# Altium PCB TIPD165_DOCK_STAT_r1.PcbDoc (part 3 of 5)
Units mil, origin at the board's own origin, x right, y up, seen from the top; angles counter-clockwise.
Board outline 6950 x 2800 mil, 2 copper layers (Primary Side, Secondary Side), stack 12.7 mil thick; 32 components, 163 nets, 1211 pads, 80 vias.
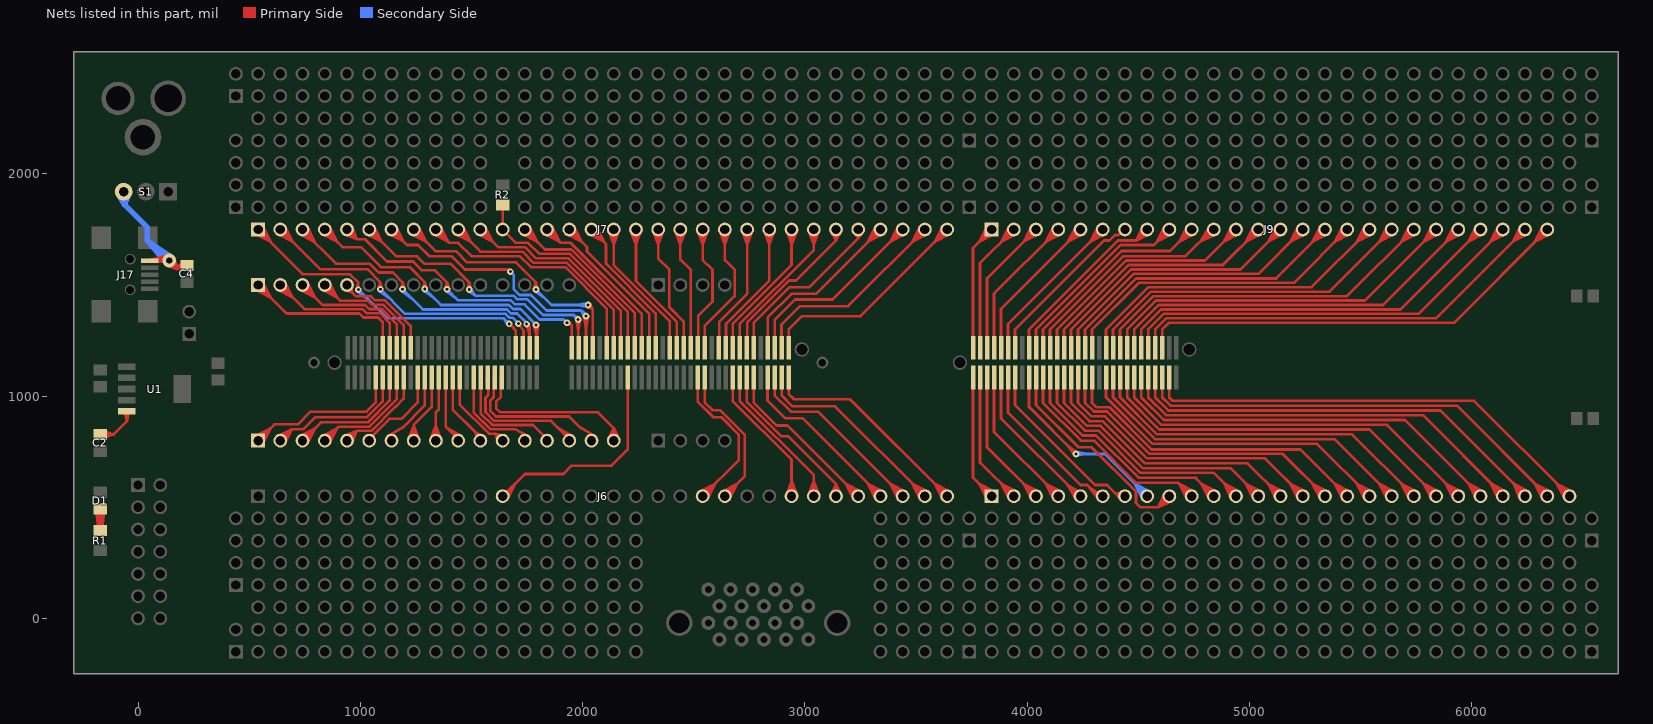
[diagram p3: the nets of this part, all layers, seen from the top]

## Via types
v1: diameter 30/30 (per signal layer), hole 13, Primary Side to Secondary Side, 70 vias
v2: diameter 62/62 (per signal layer), hole 28, Primary Side to Secondary Side, 9 vias
v3: diameter 30, hole 13, Primary Side to Secondary Side, 1 vias

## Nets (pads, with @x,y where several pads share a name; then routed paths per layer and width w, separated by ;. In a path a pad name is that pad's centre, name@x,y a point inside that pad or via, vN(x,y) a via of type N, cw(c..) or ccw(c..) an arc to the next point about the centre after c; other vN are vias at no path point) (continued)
$$$5944: J6.25 pad.103@2675.28,1084 | length 911.6
  Primary Side w12: pad.103@2675.28,1084 2675.28,978.72 2940,714 J6.25@2940,550 ; J6.25@2915.44,554.66 2940,617 ; J6.25@2927.06,551.26 2940,617 ; J6.25@2952.94,551.26 2940,617 ; J6.25@2964.56,554.66 2940,617
$$$5949: J6.26 pad.105@2706.78,1084 | length 940
  Primary Side w12: pad.105@2706.78,1084 2706.78,978.72 3040,645.5 J6.26@3040,550 ; J6.26@3015.44,554.66 3040,617 ; J6.26@3027.06,551.26 3040,617 ; J6.26@3052.94,551.26 3040,617 ; J6.26@3064.56,554.66 3040,617
$$$5959: J6.27 pad.107@2738.28,1084 | length 938.8
  Primary Side w12: pad.107@2738.28,1084 2738.28,975.26 2893.53,820 2925,820 3140,605 ; J6.27@3115.65,555.68 3140,605 ; J6.27@3127.09,551.54 3140,605 ; J6.27@3140,550 3140,605 ; J6.27@3152.91,551.54 3140,605 ; J6.27@3164.35,555.68 3140,605
$$$5970: J6.29 pad.113@2832.76,1084 | length 1190.1
  Primary Side w12: pad.113@2832.76,1084 2832.01,1084 2832.01,980 2911,901 2989,901 J6.29@3340,550 3283.54,606.46 ; J6.29@3319.77,535.31 3283.54,606.46 ; J6.29@3330.09,541.59 3283.54,606.46 ; J6.29@3348.41,559.91 3283.54,606.46 ; J6.29@3354.69,570.23 3283.54,606.46
$$$5975: J6.30 pad.115@2864.26,1084 | length 1243.8
  Primary Side w12: pad.115@2864.26,1084 2864,1083.74 2864,1003.31 2937.31,930 3060,930 J6.30@3440,550 3383.54,606.46 ; J6.30@3419.77,535.31 3383.54,606.46 ; J6.30@3430.09,541.59 3383.54,606.46 ; J6.30@3448.41,559.91 3383.54,606.46 ; J6.30@3454.69,570.23 3383.54,606.46
$$$5980: J6.31 pad.117@2895.76,1084 | length 1311.7
  Primary Side w12: pad.117@2895.76,1084 2896,1083.76 2896,1003.4 2945.26,954.15 3135.85,954.15 J6.31@3540,550 3483.54,606.46 ; J6.31@3519.77,535.31 3483.54,606.46 ; J6.31@3530.09,541.59 3483.54,606.46 ; J6.31@3548.41,559.91 3483.54,606.46 ; J6.31@3554.69,570.23 3483.54,606.46
$$$5995: J6.32 pad.119@2927.25,1084 | length 1376.4
  Primary Side w12: pad.119@2927.25,1084 2927.25,1010.22 2951.47,986 3204,986 J6.32@3640,550 3583.54,606.46 ; J6.32@3619.77,535.31 3583.54,606.46 ; J6.32@3630.09,541.59 3583.54,606.46 ; J6.32@3648.41,559.91 3583.54,606.46 ; J6.32@3654.69,570.23 3583.54,606.46
$$$6096: J6.12 pad.73@2202.84,1084 | length 1133.7
  Primary Side w12: J6.12@1640,550 1740,650 1913,650 1950,687 2130,687 2203,760 2203,907.16 2202.84,907.32 pad.73@2202.84,1084 ; J6.12@1649.91,541.59 1696.46,606.46 J6.12@1660.23,535.31
$$$6355: J7.6 pad.60@1982.37,1217.86 | length 1905.8
  Primary Side w12: J7.6@1025.31,1729.77 1096.46,1693.54 ; J7.6@1031.59,1740.09 1096.46,1693.54 ; J7.6@1040,1750 1160,1630 1160,1629 1254.99,1629 1288.99,1595 1407.23,1595 1490,1512.23 ; J7.6@1049.91,1758.41 1096.46,1693.54 ; J7.6@1060.23,1764.69 1096.46,1693.54 ; v1@1481.09,1481.26 1490,1512.23 ; v1(1490,1480) 1490,1512.23 ; v1@1498.91,1481.26 1490,1512.23 ; v1@1971.04,1344.21 1980,1294 v1@1988.96,1344.21 ; v1(1980,1345) 1980,1230 1982.37,1227.63 pad.60@1982.37,1217.86
  Secondary Side w12: v1@1484.4,1472.95 1518,1452 ; v1(1490,1480) 1518,1452 ; v1@1497.05,1485.6 1518,1452 ; v1@1972.71,1339.72 1959.85,1365.15 ; v1@1985.28,1352.29 1959.85,1365.15 ; 1518,1452 1688.06,1452 1704.06,1436 1750.82,1436 1821.67,1365.15 1959.85,1365.15 ; 1959.85,1365.15 v1(1980,1345) 1959.85,1365.15
$$$6359: J7.7 pad.62@2013.87,1217.86 | length 1788
  Primary Side w12: J7.7@1125.31,1729.77 1196.46,1693.54 ; J7.7@1131.59,1740.09 1196.46,1693.54 ; J7.7@1140,1750 1210,1680 1260,1680 1310,1630 1410,1630 1470,1570 1665,1570 v1(1675,1560) ; J7.7@1149.91,1758.41 1196.46,1693.54 ; J7.7@1160.23,1764.69 1196.46,1693.54 ; v1@2006.04,1359.21 2015,1309 ; pad.62@2013.87,1217.86 2015,1218.99 v1(2015,1360) 2015,1309 ; v1@2023.96,1359.21 2015,1309
  Secondary Side w12: v1(1675,1560) 1690,1545 1690,1482 1717,1455 1767.82,1455 1837.63,1385.19 1995,1385.19 ; v1@2007.24,1355.44 1995,1385.19 ; v1@2021.2,1366.53 1995,1385.19 ; 1995,1385.19 2015,1365.19 v1(2015,1360) 1995,1385.19
$$$6364: J7.8 pad.64@2045.36,1217.86 | length 1744.9
  Primary Side w12: J7.8@1225.31,1729.77 1296.46,1693.54 ; J7.8@1231.59,1740.09 1296.46,1693.54 ; J7.8@1240,1750 1337.77,1652.23 1430,1652.23 1480,1602.23 1700,1602.23 1790,1512.23 ; J7.8@1249.91,1758.41 1296.46,1693.54 ; J7.8@1260.23,1764.69 1296.46,1693.54 ; v1@1781.09,1481.26 1790,1512.23 ; v1(1790,1480) 1790,1512.23 ; v1@1798.91,1481.26 1790,1512.23 ; v1@2019.73,1402.7 2045,1390 ; v1(2025,1410) 2045,1390 ; v1@2032.3,1415.27 2045,1390 ; pad.64@2045.36,1217.86 2045,1218.22 2045,1390
  Secondary Side w12: v1@1784.16,1473.16 1830.46,1439.54 ; v1(1790,1480) 1860,1410 v1(2025,1410) ; v1@2024.21,1401.04 1974,1410 v1@2024.21,1418.96
$$$6375: J7.9 pad.68@2108.35,1217.86 | length 1411.2
  Primary Side w12: J7.9@1325.31,1729.77 1396.46,1693.54 ; J7.9@1331.59,1740.09 1396.46,1693.54 ; J7.9@1340,1750 1400,1690 1440,1690 1500,1630 1717,1630 1767,1580 1922.23,1580 2108.35,1393.87 pad.68@2108.35,1217.86 ; J7.9@1349.91,1758.41 1396.46,1693.54 ; J7.9@1360.23,1764.69 1396.46,1693.54
$$$6380: J7.10 pad.70@2139.85,1217.86 | length 1340
  Primary Side w12: J7.10@1425.31,1729.77 1496.46,1693.54 ; J7.10@1431.59,1740.09 1496.46,1693.54 ; J7.10@1440,1750 1540,1650 1730,1650 1780,1600 1929.1,1600 2139.85,1389.25 pad.70@2139.85,1217.86 ; J7.10@1449.91,1758.41 1496.46,1693.54 ; J7.10@1460.23,1764.69 1496.46,1693.54
$$$6388: J7.11 pad.72@2171.35,1217.86 | length 1268.8
  Primary Side w12: J7.11@1525.31,1729.77 1596.46,1693.54 ; J7.11@1531.59,1740.09 1596.46,1693.54 ; J7.11@1540,1750 1620,1670 1740,1670 1790,1620 1935.97,1620 2171.35,1384.62 pad.72@2171.35,1217.86 ; J7.11@1549.91,1758.41 1596.46,1693.54 ; J7.11@1560.23,1764.69 1596.46,1693.54
$$$6399: J7.13 pad.76@2234.34,1217.86 | length 1126.4
  Primary Side w12: J7.13@1725.31,1729.77 1796.46,1693.54 ; J7.13@1731.59,1740.09 1796.46,1693.54 ; J7.13@1740,1750 1830,1660 1949.71,1660 2234.34,1375.37 pad.76@2234.34,1217.86 ; J7.13@1749.91,1758.41 1796.46,1693.54 ; J7.13@1760.23,1764.69 1796.46,1693.54
$$$6412: J7.14 pad.78@2265.83,1217.86 | length 1055.2
  Primary Side w12: J7.14@1825.31,1729.77 1896.46,1693.54 ; J7.14@1831.59,1740.09 1896.46,1693.54 ; J7.14@1840,1750 1900,1690 1946.58,1690 2265.83,1370.74 pad.78@2265.83,1217.86 ; J7.14@1849.91,1758.41 1896.46,1693.54 ; J7.14@1860.23,1764.69 1896.46,1693.54
$$$6423: J7.15 pad.80@2297.33,1217.86 | length 1001.7
  Primary Side w12: J7.15@1925.31,1729.77 1996.46,1693.54 ; J7.15@1931.59,1740.09 1996.46,1693.54 ; J7.15@1940,1750 2020,1670 2020,1650 2300,1370 2300,1220.53 pad.80@2297.33,1217.86 ; J7.15@1949.91,1758.41 1996.46,1693.54 ; J7.15@1960.23,1764.69 1996.46,1693.54
$$$6429: J7.16 pad.82@2328.83,1217.86 | length 971.1
  Primary Side w12: J7.16@2025.31,1729.77 2096.46,1693.54 ; J7.16@2031.59,1740.09 2096.46,1693.54 ; J7.16@2040,1750 2105.2,1684.8 2105.2,1595.72 2328.83,1372.1 pad.82@2328.83,1217.86 ; J7.16@2049.91,1758.41 2096.46,1693.54 ; J7.16@2060.23,1764.69 2096.46,1693.54
$$$6435: J7.17 pad.86@2391.82,1217.86 | length 971.4
  Primary Side w12: J7.17@2115.44,1745.34 2140,1683 ; J7.17@2127.06,1748.74 2140,1683 ; J7.17@2152.94,1748.74 2140,1683 ; J7.17@2164.56,1745.34 2140,1683 ; pad.86@2391.82,1217.86 2391.82,1338.45 2140,1590.27 J7.17@2140,1750 2140,1683
$$$6440: J7.18 pad.88@2423.31,1217.86 | length 943.1
  Primary Side w12: J7.18@2215.44,1745.34 2240,1683 ; J7.18@2227.06,1748.74 2240,1683 ; J7.18@2252.94,1748.74 2240,1683 ; J7.18@2264.56,1745.34 2240,1683 ; pad.88@2423.31,1217.86 2423.31,1335.06 2240,1518.38 J7.18@2240,1750 2240,1683
$$$6444: J7.19 pad.90@2454.81,1217.86 | length 847.7
  Primary Side w12: J7.19@2315.44,1745.34 2340,1683 ; J7.19@2327.06,1748.74 2340,1683 ; J7.19@2340,1750 2340,1619 2390,1569 2390,1399.87 2454.81,1335.06 pad.90@2454.81,1217.86 ; J7.19@2352.94,1748.74 2340,1683 ; J7.19@2364.56,1745.34 2340,1683
$$$6453: J7.20 pad.92@2486.31,1217.86 | length 819.3
  Primary Side w12: J7.20@2415.44,1745.34 2440,1683 ; J7.20@2427.06,1748.74 2440,1683 ; J7.20@2440,1750 2440,1615 2486.31,1568.69 pad.92@2486.31,1217.86 ; J7.20@2452.94,1748.74 2440,1683 ; J7.20@2464.56,1745.34 2440,1683
$$$6544: J7.23 pad.100@2612.29,1217.86 | length 853
  Primary Side w12: pad.100@2612.29,1217.86 2615,1220.57 2615,1335 2740,1460 J7.23@2740,1750 ; J7.23@2715.44,1745.34 2740,1683 ; J7.23@2727.06,1748.74 2740,1683 ; J7.23@2752.94,1748.74 2740,1683 ; J7.23@2764.56,1745.34 2740,1683
$$$6550: J7.24 pad.102@2643.79,1217.86 | length 881.4
  Primary Side w12: pad.102@2643.79,1217.86 2645,1219.07 2645,1325 2840,1520 J7.24@2840,1750 ; J7.24@2815.44,1745.34 2840,1683 ; J7.24@2827.06,1748.74 2840,1683 ; J7.24@2852.94,1748.74 2840,1683 ; J7.24@2864.56,1745.34 2840,1683
$$$6590: J7.25 pad.104@2675.28,1217.86 | length 910
  Primary Side w12: pad.104@2675.28,1217.86 2675,1218.14 2675,1325 2940,1590 J7.25@2940,1750 ; J7.25@2915.44,1745.34 2940,1683 ; J7.25@2927.06,1748.74 2940,1683 ; J7.25@2952.94,1748.74 2940,1683 ; J7.25@2964.56,1745.34 2940,1683
$$$6596: J7.26 pad.106@2706.78,1217.86 | length 1005.2
  Primary Side w12: pad.106@2706.78,1217.86 2706.78,1325 3040,1658.22 J7.26@3040,1750 3040,1683 ; J7.26@3015.44,1745.34 3040,1683 ; J7.26@3027.06,1748.74 3040,1683 ; J7.26@3052.94,1748.74 3040,1683 ; J7.26@3064.56,1745.34 3040,1683
$$$6605: J7.27 pad.108@2738.28,1217.86 | length 966.4
  Primary Side w12: pad.108@2738.28,1217.86 2740,1219.58 2740,1330.57 2929.43,1520 2960,1520 3140,1700 ; J7.27@3115.79,1743.75 3140,1700 ; J7.27@3127.11,1748.31 3140,1700 ; J7.27@3152.89,1748.31 3140,1700 ; J7.27@3164.21,1743.75 3140,1700 ; 3140,1700 J7.27@3140,1750 3140,1700
$$$6625: J7.29 pad.114@2832.76,1217.86 | length 1205.9
  Primary Side w12: pad.114@2832.76,1217.86 2832.76,1352.76 2940,1460 3050,1460 J7.29@3340,1750 3283.54,1693.54 ; J7.29@3319.77,1764.69 3283.54,1693.54 ; J7.29@3330.09,1758.41 3283.54,1693.54 ; J7.29@3348.41,1740.09 3283.54,1693.54 ; J7.29@3354.69,1729.77 3283.54,1693.54
$$$6632: J7.30 pad.116@2864.26,1217.86 | length 1269
  Primary Side w12: pad.116@2864.26,1217.86 2865,1218.6 2865,1344.25 2955.75,1435 3125,1435 J7.30@3440,1750 3383.54,1693.54 ; J7.30@3419.77,1764.69 3383.54,1693.54 ; J7.30@3430.09,1758.41 3383.54,1693.54 ; J7.30@3448.41,1740.09 3383.54,1693.54 ; J7.30@3454.69,1729.77 3383.54,1693.54
$$$6638: J7.31 pad.118@2895.76,1217.86 | length 1326.3
  Primary Side w12: pad.118@2895.76,1217.86 2895,1218.61 2895,1322.63 2977.37,1405 3195,1405 J7.31@3540,1750 3483.54,1693.54 ; J7.31@3519.77,1764.69 3483.54,1693.54 ; J7.31@3530.09,1758.41 3483.54,1693.54 ; J7.31@3548.41,1740.09 3483.54,1693.54 ; J7.31@3554.69,1729.77 3483.54,1693.54
$$$6644: J7.32 pad.120@2927.25,1217.86 | length 1380.5
  Primary Side w12: pad.120@2927.25,1217.86 2927.25,1300 2987.25,1360 3250,1360 J7.32@3640,1750 3583.54,1693.54 ; J7.32@3619.77,1764.69 3583.54,1693.54 ; J7.32@3630.09,1758.41 3583.54,1693.54 ; J7.32@3648.41,1740.09 3583.54,1693.54 ; J7.32@3654.69,1729.77 3583.54,1693.54
$$$6817: pad.1@3840,550 pad.121@3756.7,1084 | length 967.7
  Primary Side w12: pad.121@3756.7,1084 3756.7,633.3 pad.1@3840,550 3783.54,606.46 ; pad.1@3819.77,535.31 3783.54,606.46 ; pad.1@3830.09,541.59 3783.54,606.46 ; pad.1@3848.41,559.91 3783.54,606.46 ; pad.1@3854.69,570.23 3783.54,606.46
$$$6833: pad.2@3940,550 pad.123@3788.2,1084 | length 997.1
  Primary Side w12: pad.123@3788.2,1084 3788.2,700 3790,700 pad.2@3940,550 3883.54,606.46 ; pad.2@3919.77,535.31 3883.54,606.46 ; pad.2@3930.09,541.59 3883.54,606.46 ; pad.2@3948.41,559.91 3883.54,606.46 ; pad.2@3954.69,570.23 3883.54,606.46
$$$6839: pad.3@4040,550 pad.125@3819.69,1084 | length 1024.6
  Primary Side w12: pad.125@3819.69,1084 3819.69,770 3820,770 pad.3@4040,550 3983.54,606.46 ; pad.3@4019.77,535.31 3983.54,606.46 ; pad.3@4030.09,541.59 3983.54,606.46 ; pad.3@4048.41,559.91 3983.54,606.46 ; pad.3@4054.69,570.23 3983.54,606.46
$$$6845: pad.4@4140,550 pad.127@3851.19,1084 | length 1052.8
  Primary Side w12: pad.127@3851.19,1084 3851.19,838.81 pad.4@4140,550 4083.54,606.46 ; pad.4@4119.77,535.31 4083.54,606.46 ; pad.4@4130.09,541.59 4083.54,606.46 ; pad.4@4148.41,559.91 4083.54,606.46 ; pad.4@4154.69,570.23 4083.54,606.46
$$$6852: pad.5@4240,550 pad.129@3882.69,1084 | length 1005.7
  Primary Side w12: pad.129@3882.69,1084 3882.69,900 4232.69,550 pad.5@4240,550 4180,602.69 ; pad.5@4220.77,534.03 4180,602.69 ; pad.5@4230.66,540.96 4180,602.69 ; pad.5@4247.75,560.43 4180,602.69
$$$6856: pad.6@4340,550 pad.131@3914.18,1084 | length 968.2
  Primary Side w12: pad.131@3914.18,1084 3914.18,925.82 4240,600 4270,600 4320,550 pad.6@4340,550 4277.06,592.94 ; pad.6@4322.71,531.94 4277.06,592.94 ; pad.6@4331.78,539.93 4277.06,592.94
$$$6862: pad.7@4440,550 pad.133@3945.68,1084 | length 994.3
  Primary Side w12: pad.133@3945.68,1084 3945.68,960 4305.68,600 4360,600 4400,560 ; pad.7@4426.87,528.73 4400,560 ; pad.7@4434.9,538.04 4400,560 ; pad.7@4438.43,574.95 4400,560 ; pad.7@4441.13,562.95 4400,560 ; 4400,560 4430,560 pad.7@4440,550 4400,560
$$$6865: pad.8@4540,550 pad.137@4008.67,1084 | length 1503.9
  Primary Side w12: pad.137@4008.67,1084 4008.67,950 4010,950 v1(4220,740) 4179.54,780.46 ; v1@4213.16,734.16 4179.54,780.46 ; v1@4225.84,746.84 4179.54,780.46
  Secondary Side w12: v1(4220,740) 4350,740 pad.8@4540,550 4483.54,606.46 ; v1@4220.79,731.04 4271,740 v1@4220.79,748.96 ; pad.8@4519.77,535.31 4483.54,606.46 ; pad.8@4530.09,541.59 4483.54,606.46 ; pad.8@4548.41,559.91 4483.54,606.46 ; pad.8@4554.69,570.23 4483.54,606.46
$$$6870: pad.9@4640,550 pad.139@4040.17,1084 | length 1247.2
  Primary Side w12: pad.139@4040.17,1084 4040.17,960 4230.08,770.08 4289.92,770.08 4490,570 4490,520 4510,500 4590,500 ; pad.9@4619.48,564.27 4590,500 ; pad.9@4630,558.31 4590,500 ; pad.9@4640,550 4590,500 ; pad.9@4648.31,540 4590,500 ; pad.9@4654.27,529.48 4590,500
$$$6874: pad.10@4740,550 pad.141@4071.66,1084 | length 1355.5
  Primary Side w12: pad.141@4071.66,1084 4071.66,970 4241.66,800 4300,800 4490,610 4680,610 pad.10@4740,550 4683.54,606.46 ; pad.10@4719.77,535.31 4683.54,606.46 ; pad.10@4730.09,541.59 4683.54,606.46 ; pad.10@4748.41,559.91 4683.54,606.46 ; pad.10@4754.69,570.23 4683.54,606.46
$$$6877: pad.11@4840,550 pad.143@4103.16,1084 | length 1425.9
  Primary Side w12: pad.143@4103.16,1084 4103.16,970 4250,823.16 4310,823.16 4500,633.16 4760,633.16 4760,630 pad.11@4840,550 4783.54,606.46 ; pad.11@4819.77,535.31 4783.54,606.46 ; pad.11@4830.09,541.59 4783.54,606.46 ; pad.11@4848.41,559.91 4783.54,606.46 ; pad.11@4854.69,570.23 4783.54,606.46
$$$6881: pad.12@4940,550 pad.145@4134.65,1084 | length 1491.1
  Primary Side w12: pad.145@4134.65,1084 4134.65,970 4260,844.65 4320,844.65 4510,654.65 4840,654.65 4940,554.65 pad.12@4940,550 4886.51,608.14 ; pad.12@4919.15,536.2 4886.51,608.14 ; pad.12@4929.74,542.02 4886.51,608.14 ; pad.12@4948.81,559.56 4886.51,608.14 ; pad.12@4955.49,569.62 4886.51,608.14
$$$6885: pad.13@5040,550 pad.147@4166.15,1084 | length 1561
  Primary Side w12: pad.147@4166.15,1084 4166.15,970 4270,866.15 4330,866.15 4520,676.15 4913.85,676.15 pad.13@5040,550 4983.54,606.46 ; pad.13@5019.77,535.31 4983.54,606.46 ; pad.13@5030.09,541.59 4983.54,606.46 ; pad.13@5048.41,559.91 4983.54,606.46 ; pad.13@5054.69,570.23 4983.54,606.46
$$$6888: pad.14@5140,550 pad.149@4197.65,1084 | length 1629.5
  Primary Side w12: pad.149@4197.65,1084 4197.65,970 4280,887.65 4340,887.65 4530,697.65 4992.35,697.65 pad.14@5140,550 5083.54,606.46 ; pad.14@5119.77,535.31 5083.54,606.46 ; pad.14@5130.09,541.59 5083.54,606.46 ; pad.14@5148.41,559.91 5083.54,606.46 ; pad.14@5154.69,570.23 5083.54,606.46
$$$6893: pad.15@5240,550 pad.151@4229.14,1084 | length 1698
  Primary Side w12: pad.151@4229.14,1084 4229.14,970 4290,909.14 4350.86,909.14 4540,720 5070,720 pad.15@5240,550 5183.54,606.46 ; pad.15@5219.77,535.31 5183.54,606.46 ; pad.15@5230.09,541.59 5183.54,606.46 ; pad.15@5248.41,559.91 5183.54,606.46 ; pad.15@5254.69,570.23 5183.54,606.46
$$$6907: pad.16@5340,550 pad.153@4260.64,1084 | length 1766.9
  Primary Side w12: pad.153@4260.64,1084 4260.64,970 4300,930.64 4360,930.64 4550,740.64 5150,740.64 5150,740 pad.16@5340,550 5283.54,606.46 ; pad.16@5319.77,535.31 5283.54,606.46 ; pad.16@5330.09,541.59 5283.54,606.46 ; pad.16@5348.41,559.91 5283.54,606.46 ; pad.16@5354.69,570.23 5283.54,606.46
$$$6912: pad.17@5440,550 pad.155@4292.13,1084 | length 1835
  Primary Side w12: pad.155@4292.13,1084 4292.13,970 4312.13,950 4370,950 4560,760 5230,760 pad.17@5440,550 5383.54,606.46 ; pad.17@5419.77,535.31 5383.54,606.46 ; pad.17@5430.09,541.59 5383.54,606.46 ; pad.17@5448.41,559.91 5383.54,606.46 ; pad.17@5454.69,570.23 5383.54,606.46
$$$6919: pad.18@5540,550 pad.159@4355.13,1084 | length 1857.4
  Primary Side w12: pad.159@4355.13,1084 4355.13,995 4565,785.13 5304.87,785.13 pad.18@5540,550 5483.54,606.46 ; pad.18@5519.77,535.31 5483.54,606.46 ; pad.18@5530.09,541.59 5483.54,606.46 ; pad.18@5548.41,559.91 5483.54,606.46 ; pad.18@5554.69,570.23 5483.54,606.46
$$$6927: pad.19@5640,550 pad.161@4386.62,1084 | length 1925.9
  Primary Side w12: pad.161@4386.62,1084 4386.62,995 4575,806.62 5383.38,806.62 pad.19@5640,550 5583.54,606.46 ; pad.19@5619.77,535.31 5583.54,606.46 ; pad.19@5630.09,541.59 5583.54,606.46 ; pad.19@5648.41,559.91 5583.54,606.46 ; pad.19@5654.69,570.23 5583.54,606.46
$$$6931: pad.20@5740,550 pad.163@4418.12,1084 | length 1994.4
  Primary Side w12: pad.163@4418.12,1084 4418.12,995 4585,828.12 5461.88,828.12 pad.20@5740,550 5683.54,606.46 ; pad.20@5719.77,535.31 5683.54,606.46 ; pad.20@5730.09,541.59 5683.54,606.46 ; pad.20@5748.41,559.91 5683.54,606.46 ; pad.20@5754.69,570.23 5683.54,606.46
$$$6934: pad.21@5840,550 pad.165@4449.61,1084 | length 2063.1
  Primary Side w12: pad.165@4449.61,1084 4449.61,995 4585,859.61 4585,859.23 4594.61,849.61 5540.39,849.61 pad.21@5840,550 5783.54,606.46 ; pad.21@5819.77,535.31 5783.54,606.46 ; pad.21@5830.09,541.59 5783.54,606.46 ; pad.21@5848.41,559.91 5783.54,606.46 ; pad.21@5854.69,570.23 5783.54,606.46
$$$6938: pad.22@5940,550 pad.167@4481.11,1084 | length 2131.4
  Primary Side w12: pad.167@4481.11,1084 4481.11,995 4605,871.11 5618.89,871.11 pad.22@5940,550 5883.54,606.46 ; pad.22@5919.77,535.31 5883.54,606.46 ; pad.22@5930.09,541.59 5883.54,606.46 ; pad.22@5948.41,559.91 5883.54,606.46 ; pad.22@5954.69,570.23 5883.54,606.46
$$$6943: pad.23@6040,550 pad.169@4512.61,1084 | length 2200.9
  Primary Side w12: pad.169@4512.61,1084 4512.61,995 4615,892.61 5700,892.61 6040,552.61 pad.23@6040,550 5984.94,607.66 ; pad.23@6019.44,535.78 5984.94,607.66 ; pad.23@6029.9,541.82 5984.94,607.66 ; pad.23@6048.64,559.71 5984.94,607.66 ; pad.23@6055.15,569.89 5984.94,607.66
$$$6947: pad.24@6140,550 pad.171@4544.1,1084 | length 2270.3
  Primary Side w12: pad.171@4544.1,1084 4544.1,995 4625,914.1 5780,914.1 6140,554.1 pad.24@6140,550 6085.71,608.39 ; pad.24@6119.25,536.06 6085.71,608.39 ; pad.24@6129.79,541.95 6085.71,608.39 ; pad.24@6148.77,559.6 6085.71,608.39 ; pad.24@6155.41,569.68 6085.71,608.39
$$$6955: pad.25@6240,550 pad.173@4575.6,1084 | length 2339.9
  Primary Side w12: pad.173@4575.6,1084 4575.6,995 4635,935.6 5860,935.6 6240,555.6 pad.25@6240,550 6186.45,609.15 ; pad.25@6219.07,536.33 6186.45,609.15 ; pad.25@6229.68,542.09 6186.45,609.15 ; pad.25@6248.89,559.48 6186.45,609.15 ; pad.25@6255.68,569.48 6186.45,609.15
$$$6959: pad.26@6340,550 pad.175@4607.09,1084 | length 2405.4
  Primary Side w12: pad.175@4607.09,1084 4607.09,995 4645,957.09 5932.91,957.09 pad.26@6340,550 6283.54,606.46 ; pad.26@6319.77,535.31 6283.54,606.46 ; pad.26@6330.09,541.59 6283.54,606.46 ; pad.26@6348.41,559.91 6283.54,606.46 ; pad.26@6354.69,570.23 6283.54,606.46
$$$6985: J9.1 pad.122@3756.7,1217.86 | length 965.8
  Primary Side w12: pad.122@3756.7,1217.86 3756.7,1666.7 J9.1@3840,1750 3783.54,1693.54 ; J9.1@3819.77,1764.69 3783.54,1693.54 ; J9.1@3830.09,1758.41 3783.54,1693.54 ; J9.1@3848.41,1740.09 3783.54,1693.54 ; J9.1@3854.69,1729.77 3783.54,1693.54
$$$7008: J9.2 pad.124@3788.2,1217.86 | length 994.2
  Primary Side w12: pad.124@3788.2,1217.86 3788.2,1598.2 J9.2@3940,1750 3883.54,1693.54 ; J9.2@3919.77,1764.69 3883.54,1693.54 ; J9.2@3930.09,1758.41 3883.54,1693.54 ; J9.2@3948.41,1740.09 3883.54,1693.54 ; J9.2@3954.69,1729.77 3883.54,1693.54
$$$7013: J9.3 pad.126@3819.69,1217.86 | length 1022.8
  Primary Side w12: pad.126@3819.69,1217.86 3819.69,1530 3820,1530 J9.3@4040,1750 3983.54,1693.54 ; J9.3@4019.77,1764.69 3983.54,1693.54 ; J9.3@4030.09,1758.41 3983.54,1693.54 ; J9.3@4048.41,1740.09 3983.54,1693.54 ; J9.3@4054.69,1729.77 3983.54,1693.54
$$$7019: J9.4 pad.128@3851.19,1217.86 | length 1051
  Primary Side w12: pad.128@3851.19,1217.86 3851.19,1461.19 J9.4@4140,1750 4083.54,1693.54 ; J9.4@4119.77,1764.69 4083.54,1693.54 ; J9.4@4130.09,1758.41 4083.54,1693.54 ; J9.4@4148.41,1740.09 4083.54,1693.54 ; J9.4@4154.69,1729.77 4083.54,1693.54
$$$7023: J9.5 pad.130@3882.69,1217.86 | length 1079.3
  Primary Side w12: pad.130@3882.69,1217.86 3882.69,1392.69 J9.5@4240,1750 4183.54,1693.54 ; J9.5@4219.77,1764.69 4183.54,1693.54 ; J9.5@4230.09,1758.41 4183.54,1693.54 ; J9.5@4248.41,1740.09 4183.54,1693.54 ; J9.5@4254.69,1729.77 4183.54,1693.54
$$$7027: J9.6 pad.132@3914.18,1217.86 | length 1107.7
  Primary Side w12: pad.132@3914.18,1217.86 3914.18,1324.18 J9.6@4340,1750 4283.54,1693.54 ; J9.6@4319.77,1764.69 4283.54,1693.54 ; J9.6@4330.09,1758.41 4283.54,1693.54 ; J9.6@4348.41,1740.09 4283.54,1693.54 ; J9.6@4354.69,1729.77 4283.54,1693.54
$$$7032: J9.7 pad.134@3945.68,1217.86 | length 762.9
  Primary Side w12: pad.134@3945.68,1217.86 3945.68,1300 4345.68,1700 4370,1700 4395,1725 4410,1725 4435,1750 J9.7@4440,1750
$$$7038: J9.8 pad.138@4008.67,1217.86 | length 1082.7
  Primary Side w12: pad.138@4008.67,1217.86 4008.67,1300 4408.67,1700 4490,1700 ; J9.8@4519.48,1764.27 4490,1700 ; J9.8@4530,1758.31 4490,1700 ; J9.8@4540,1750 4490,1700 ; J9.8@4548.31,1740 4490,1700 ; J9.8@4554.27,1729.48 4490,1700
$$$7041: J9.9 pad.140@4040.17,1217.86 | length 1267.6
  Primary Side w12: pad.140@4040.17,1217.86 4040.17,1300 4420.08,1679.92 4570,1679.92 4570,1680 J9.9@4640,1750 4583.54,1693.54 ; J9.9@4619.77,1764.69 4583.54,1693.54 ; J9.9@4630.09,1758.41 4583.54,1693.54 ; J9.9@4648.41,1740.09 4583.54,1693.54 ; J9.9@4654.69,1729.77 4583.54,1693.54
$$$7063: J9.10 pad.142@4071.66,1217.86 | length 1336.1
  Primary Side w12: pad.142@4071.66,1217.86 4071.66,1300 4424.36,1652.7 4642.7,1652.7 J9.10@4740,1750 4683.54,1693.54 ; J9.10@4719.77,1764.69 4683.54,1693.54 ; J9.10@4730.09,1758.41 4683.54,1693.54 ; J9.10@4748.41,1740.09 4683.54,1693.54 ; J9.10@4754.69,1729.77 4683.54,1693.54
$$$7068: J9.11 pad.144@4103.16,1217.86 | length 1400.3
  Primary Side w12: pad.144@4103.16,1217.86 4103.16,1300 4433.16,1630 4713.16,1630 4833.16,1750 J9.11@4840,1750 4780.83,1697.68 ; J9.11@4820.68,1765.87 4780.83,1697.68 ; J9.11@4830.62,1759 4780.83,1697.68 ; J9.11@4847.78,1739.59 4780.83,1697.68 ; J9.11@4853.39,1728.89 4780.83,1697.68
$$$7071: J9.12 pad.146@4134.65,1217.86 | length 1473.1
  Primary Side w12: pad.146@4134.65,1217.86 4134.65,1300 4444.65,1610 4800,1610 J9.12@4940,1750 4883.54,1693.54 ; J9.12@4919.77,1764.69 4883.54,1693.54 ; J9.12@4930.09,1758.41 4883.54,1693.54 ; J9.12@4948.41,1740.09 4883.54,1693.54 ; J9.12@4954.69,1729.77 4883.54,1693.54
$$$7074: J9.13 pad.148@4166.15,1217.86 | length 1541.6
  Primary Side w12: pad.148@4166.15,1217.86 4166.15,1300 4456.15,1590 4880,1590 J9.13@5040,1750 4983.54,1693.54 ; J9.13@5019.77,1764.69 4983.54,1693.54 ; J9.13@5030.09,1758.41 4983.54,1693.54 ; J9.13@5048.41,1740.09 4983.54,1693.54 ; J9.13@5054.69,1729.77 4983.54,1693.54
$$$7078: J9.14 pad.150@4197.65,1217.86 | length 1610.1
  Primary Side w12: pad.150@4197.65,1217.86 4197.65,1300 4467.65,1570 4960,1570 J9.14@5140,1750 5083.54,1693.54 ; J9.14@5119.77,1764.69 5083.54,1693.54 ; J9.14@5130.09,1758.41 5083.54,1693.54 ; J9.14@5148.41,1740.09 5083.54,1693.54 ; J9.14@5154.69,1729.77 5083.54,1693.54
$$$7081: J9.15 pad.152@4229.14,1217.86 | length 1678.6
  Primary Side w12: pad.152@4229.14,1217.86 4229.14,1300 4479.14,1550 5040,1550 J9.15@5240,1750 5183.54,1693.54 ; J9.15@5219.77,1764.69 5183.54,1693.54 ; J9.15@5230.09,1758.41 5183.54,1693.54 ; J9.15@5248.41,1740.09 5183.54,1693.54 ; J9.15@5254.69,1729.77 5183.54,1693.54
$$$7095: J9.16 pad.154@4260.64,1217.86 | length 1747.5
  Primary Side w12: pad.154@4260.64,1217.86 4260.64,1300 4490,1529.36 5120,1529.36 5120,1530 J9.16@5340,1750 5283.54,1693.54 ; J9.16@5319.77,1764.69 5283.54,1693.54 ; J9.16@5330.09,1758.41 5283.54,1693.54 ; J9.16@5348.41,1740.09 5283.54,1693.54 ; J9.16@5354.69,1729.77 5283.54,1693.54
$$$7099: J9.17 pad.156@4292.13,1217.86 | length 1815.6
  Primary Side w12: pad.156@4292.13,1217.86 4292.13,1300 4502.13,1510 5200,1510 J9.17@5440,1750 5383.54,1693.54 ; J9.17@5419.77,1764.69 5383.54,1693.54 ; J9.17@5430.09,1758.41 5383.54,1693.54 ; J9.17@5448.41,1740.09 5383.54,1693.54 ; J9.17@5454.69,1729.77 5383.54,1693.54
$$$7111: J9.18 pad.160@4355.13,1217.86 | length 1852.6
  Primary Side w12: pad.160@4355.13,1217.86 4355.13,1300 4545.13,1490 5280,1490 J9.18@5540,1750 5483.54,1693.54 ; J9.18@5519.77,1764.69 5483.54,1693.54 ; J9.18@5530.09,1758.41 5483.54,1693.54 ; J9.18@5548.41,1740.09 5483.54,1693.54 ; J9.18@5554.69,1729.77 5483.54,1693.54
$$$7115: J9.19 pad.162@4386.62,1217.86 | length 1921.1
  Primary Side w12: pad.162@4386.62,1217.86 4386.62,1300 4556.62,1470 5360,1470 J9.19@5640,1750 5583.54,1693.54 ; J9.19@5619.77,1764.69 5583.54,1693.54 ; J9.19@5630.09,1758.41 5583.54,1693.54 ; J9.19@5648.41,1740.09 5583.54,1693.54 ; J9.19@5654.69,1729.77 5583.54,1693.54
$$$7120: J9.20 pad.164@4418.12,1217.86 | length 1989.6
  Primary Side w12: pad.164@4418.12,1217.86 4418.12,1300 4568.12,1450 5440,1450 J9.20@5740,1750 5683.54,1693.54 ; J9.20@5719.77,1764.69 5683.54,1693.54 ; J9.20@5730.09,1758.41 5683.54,1693.54 ; J9.20@5748.41,1740.09 5683.54,1693.54 ; J9.20@5754.69,1729.77 5683.54,1693.54
$$$7124: J9.21 pad.166@4449.61,1217.86 | length 2058.1
  Primary Side w12: pad.166@4449.61,1217.86 4450,1218.24 4450,1300.39 4580,1430.39 5520.39,1430.39 J9.21@5840,1750 5783.54,1693.54 ; J9.21@5819.77,1764.69 5783.54,1693.54 ; J9.21@5830.09,1758.41 5783.54,1693.54 ; J9.21@5848.41,1740.09 5783.54,1693.54 ; J9.21@5854.69,1729.77 5783.54,1693.54
$$$7129: J9.22 pad.168@4481.11,1217.86 | length 2126.6
  Primary Side w12: pad.168@4481.11,1217.86 4481.11,1300 4591.11,1410 5600,1410 J9.22@5940,1750 5883.54,1693.54 ; J9.22@5919.77,1764.69 5883.54,1693.54 ; J9.22@5930.09,1758.41 5883.54,1693.54 ; J9.22@5948.41,1740.09 5883.54,1693.54 ; J9.22@5954.69,1729.77 5883.54,1693.54
$$$7134: J9.23 pad.170@4512.61,1217.86 | length 2195.1
  Primary Side w12: pad.170@4512.61,1217.86 4512.61,1300 4602.61,1390 5680,1390 J9.23@6040,1750 5983.54,1693.54 ; J9.23@6019.77,1764.69 5983.54,1693.54 ; J9.23@6030.09,1758.41 5983.54,1693.54 ; J9.23@6048.41,1740.09 5983.54,1693.54 ; J9.23@6054.69,1729.77 5983.54,1693.54
$$$7139: J9.24 pad.172@4544.1,1217.86 | length 2263.6
  Primary Side w12: pad.172@4544.1,1217.86 4544.1,1300 4614.1,1370 5760,1370 J9.24@6140,1750 6083.54,1693.54 ; J9.24@6119.77,1764.69 6083.54,1693.54 ; J9.24@6130.09,1758.41 6083.54,1693.54 ; J9.24@6148.41,1740.09 6083.54,1693.54 ; J9.24@6154.69,1729.77 6083.54,1693.54
$$$7143: J9.25 pad.174@4575.6,1217.86 | length 2332.1
  Primary Side w12: pad.174@4575.6,1217.86 4575.6,1300 4625.6,1350 5840,1350 J9.25@6240,1750 6183.54,1693.54 ; J9.25@6219.77,1764.69 6183.54,1693.54 ; J9.25@6230.09,1758.41 6183.54,1693.54 ; J9.25@6248.41,1740.09 6183.54,1693.54 ; J9.25@6254.69,1729.77 6183.54,1693.54
$$$7149: J9.26 pad.176@4607.09,1217.86 | length 2400.6
  Primary Side w12: pad.176@4607.09,1217.86 4607.09,1300 4637.09,1330 5920,1330 J9.26@6340,1750 6283.54,1693.54 ; J9.26@6319.77,1764.69 6283.54,1693.54 ; J9.26@6330.09,1758.41 6283.54,1693.54 ; J9.26@6348.41,1740.09 6283.54,1693.54 ; J9.26@6354.69,1729.77 6283.54,1693.54
$$$13691: J7.12 pad.74@2202.84,1217.86 R2.1 | length 988.2
  Primary Side w12: R2.1@1640,1860 J7.12@1640,1750 1700,1690 1755,1690 1805,1640 1942.84,1640 2202.84,1379.99 pad.74@2202.84,1217.86
$$$13732: J7.1 pad.50@1698.91,1217.86 | length 1933.1
  Primary Side w12: J7.1@525.31,1729.77 596.46,1693.54 ; J7.1@531.59,1740.09 596.46,1693.54 ; J7.1@540,1750 740,1550 740,1548 954.23,1548 991,1511.23 ; J7.1@549.91,1758.41 596.46,1693.54 ; J7.1@560.23,1764.69 596.46,1693.54 ; v1@982.09,1480.26 991,1511.23 ; v1(991,1479) 991,1511.23 ; v1@1671.06,1326.06 v1(1670,1325) 1672.11,1325 1690.25,1306.86 1690.25,1304.75 1698.91,1296.09 pad.50@1698.91,1217.86 pad.50@1702.19,1217.86
  Secondary Side w12: v1@985.16,1472.16 1031.46,1438.54 ; v1(991,1479) 1119,1351 1644.6,1351 ; v1@1662.83,1319.56 1644.6,1351 ; 1644.6,1351 1670,1325.6 v1(1670,1325) 1644.6,1351
$$$13740: J7.2 pad.52@1730.4,1217.86 | length 1828.8
  Primary Side w12: J7.2@625.31,1729.77 696.46,1693.54 ; J7.2@631.59,1740.09 696.46,1693.54 ; J7.2@640,1750 819,1571 1031.23,1571 1090,1512.23 ; J7.2@649.91,1758.41 696.46,1693.54 ; J7.2@660.23,1764.69 696.46,1693.54 ; v1@1081.09,1482.3 1090,1512.23 ; v1(1090,1481) 1090,1512.23 ; v1@1098.91,1482.3 1090,1512.23 ; v1@1707.07,1322.07 v1(1711,1326) 1733.96,1295.19 1733.96,1217.86 pad.52@1730.4,1217.86
  Secondary Side w12: v1@1084.16,1474.16 1130.46,1440.54 ; v1(1090,1481) 1201,1370 1652.94,1370 1669.94,1353 1684,1353 v1(1711,1326)
$$$13745: J7.3 pad.54@1761.9,1217.86 | length 1953.2
  Primary Side w12: J7.3@724.61,1730.29 794.1,1691.9 ; J7.3@731.24,1740.39 794.1,1691.9 ; J7.3@750.21,1758.05 794.1,1691.9 ; J7.3@760.75,1763.94 794.1,1691.9 ; v1@1181.09,1482.3 1190,1512.23 ; v1(1190,1481) 1190,1512.23 ; v1@1198.91,1482.3 1190,1512.23 ; v1@1756.87,1325.5 1761.9,1268.83 v1(1748,1324) 1761.9,1310.1 pad.54@1761.9,1217.86 ; 794.1,1691.9 J7.3@740,1750 740,1746 890,1596 1041.79,1596 1081.79,1556 1146.23,1556 1190,1512.23
  Secondary Side w12: v1@1184.16,1474.16 1230.46,1440.54 ; v1(1190,1481) 1281,1390 1660.52,1390 1678.52,1372 1705.82,1372 1750.91,1326.91 v1(1748,1324)
$$$13750: J7.4 pad.56@1793.39,1217.86 | length 1841.3
  Primary Side w12: J7.4@825.31,1729.77 896.46,1693.54 ; J7.4@831.59,1740.09 896.46,1693.54 ; J7.4@840,1750 920,1670 1002.24,1670 1092.24,1580 1222.23,1580 1290,1512.23 ; J7.4@849.91,1758.41 896.46,1693.54 ; J7.4@860.23,1764.69 896.46,1693.54 ; v1@1281.1,1483.34 1290,1512.23 ; v1(1290,1482) 1290,1512.23 ; v1@1298.9,1483.34 1290,1512.23 ; v1@1781.11,1318.63 pad.56@1793.39,1268.59 ; pad.56@1793.39,1217.86 1793.39,1315 v1(1790,1320) pad.56@1793.39,1268.59 ; v1@1799,1319.81 pad.56@1793.39,1268.59
  Secondary Side w12: v1@1284.16,1475.16 1330.46,1441.54 ; v1(1290,1482) 1362,1410 1668.7,1410 1686.7,1392 1719.82,1392 1786.91,1324.91 v1(1790,1320)
$$$13755: J7.5 pad.58@1950.87,1217.86 | length 1748
  Primary Side w12: J7.5@926.25,1729.12 983.88,1706.12 ; J7.5@931.82,1739.9 983.88,1706.12 ; J7.5@940,1750 983.88,1706.12 ; J7.5@950.1,1758.18 983.88,1706.12 ; J7.5@960.88,1763.75 983.88,1706.12 ; v1@1381.09,1482.3 1390,1512.23 ; v1(1390,1481) 1390,1512.23 ; v1@1398.91,1482.3 1390,1512.23 ; v1@1927.41,1321.38 1951,1319 ; v1@1935.61,1337.03 1951,1319 ; pad.58@1950.87,1217.86 1951,1217.98 1951,1319 ; 983.88,1706.12 1019.88,1706.12 1120,1606 1237.33,1606 1277.33,1566 1336.23,1566 1390,1512.23 ; 1951,1319 1940,1330 v1(1930,1330) 1951,1319
  Secondary Side w12: v1@1384.16,1474.16 1430.46,1440.54 ; v1(1390,1481) 1440,1431 1677.12,1431 1695.12,1413 1739.07,1413 1807.07,1345 1915,1345 v1(1930,1330)
$$$15332: C2.2 U1.5 | length 603.3
  Primary Side w12: C2.2@-170,827.5 -110,827.5 ; C2.2@-166,827.5 -110,827.5 ; C2.2@-165.5,820.02 -110,827.5 ; C2.2@-165.5,834.98 -110,827.5 ; C2.2@-162.6,808.3 -110,827.5 ; C2.2@-162.6,846.7 -110,827.5 ; U1.5@-59.93,930.89 -50,887.5 ; U1.5@-42.03,931.29 -50,887.5 ; -110,827.5 -50,887.5 ; -50,887.5 -50,931 U1.5@-51,932 -50,887.5
$$$15561: D1.2 R1.2 | length 292.5
  Primary Side w25: D1.2@-182.97,491.63 R1.2@-170,395 ; D1.2@-170,492.5 R1.2@-170,395 ; D1.2@-157.03,491.63 R1.2@-170,395
$$$17719: J6.21 pad.93@2517.8,1084 | length 1018.4
  Primary Side w12: pad.93@2517.8,1084 2517.8,975.73 2588.53,905 2624.1,905 2703,826.1 2703,713 J6.21@2540,550 ; J6.21@2525.31,570.23 2596.46,606.46 ; J6.21@2531.59,559.91 2596.46,606.46 ; J6.21@2549.91,541.59 2596.46,606.46 ; J6.21@2560.23,535.31 2596.46,606.46
$$$17823: J6.28 pad.109@2769.77,1084 | length 1157
  Primary Side w12: pad.109@2769.77,1084 2769.77,970.63 2872.4,868 2922,868 J6.28@3240,550 3183.54,606.46 ; J6.28@3219.77,535.31 3183.54,606.46 ; J6.28@3230.09,541.59 3183.54,606.46 ; J6.28@3248.41,559.91 3183.54,606.46 ; J6.28@3254.69,570.23 3183.54,606.46
$$$17957: J7.28 pad.110@2769.77,1217.86 | length 979.8
  Primary Side w12: pad.110@2769.77,1217.86 2769.77,1330 2929.77,1490 3020,1490 3240,1710 ; J7.28@3216.25,1742.19 3240,1710 ; J7.28@3227.17,1747.89 3240,1710 ; J7.28@3252.83,1747.89 3240,1710 ; J7.28@3263.75,1742.19 3240,1710 ; 3240,1710 J7.28@3240,1750 3240,1710
$$$17999: J7.21 pad.94@2517.8,1217.86 | length 845.8
  Primary Side w12: J7.21@2515.44,1745.34 2540,1683 ; pad.94@2517.8,1217.86 2520,1220.06 2520,1361 2584,1425 2584,1568.69 2540,1612.69 J7.21@2540,1750 ; J7.21@2527.06,1748.74 2540,1683 ; J7.21@2552.94,1748.74 2540,1683 ; J7.21@2564.56,1745.34 2540,1683
$$$19747: J7.22 pad.96@2549.3,1217.86 | length 874.2
  Primary Side w12: pad.96@2549.3,1217.86 2549.3,1315.3 2684,1450 2684,1568.69 2640,1612.69 J7.22@2640,1750 ; J7.22@2615.44,1745.34 2640,1683 ; J7.22@2627.06,1748.74 2640,1683 ; J7.22@2652.94,1748.74 2640,1683 ; J7.22@2664.56,1745.34 2640,1683
$$$20820: C4.2 J17.1 S1.3 | length 1675.4
  Primary Side w12: C4.2@218.75,1575 218.75,1586.25 C4.2@220,1587.5
  Primary Side w20: v2@128.64,1592.34 175,1575 ; v2@136.13,1630.64 J17.1@83,1609.99 ; v2@137.46,1630.85 J17.1@53,1609.99 ; v2@157.66,1621.36 175,1575 ; C4.2@208.87,1601.26 175,1575 ; C4.2@216,1587.5 175,1575 ; C4.2@217.76,1572.1 175,1575 ; C4.2@218.75,1575 175,1575 ; J17.1@53,1609.99 v2@122,1609.99 ; J17.1@53,1609.99 v2(140,1610) ; J17.1@83,1609.99 v2@122,1609.99 ; J17.1@83,1609.99 v2(140,1610) ; v2@122,1609.99 v2(140,1610) ; v2(140,1610) 175,1575
  Secondary Side w12: S1.3@-65,1920 S1.3@-61.5,1916.5
  Secondary Side w25: S1.3@-91.3,1911.96 -61.5,1861.5 ; S1.3@-65,1920 -61.5,1861.5 ; S1.3@-61.5,1916.5 -61.5,1861.5 ; S1.3@-37.93,1915.15 -61.5,1861.5 ; v2@126.52,1597.33 53.09,1688.91 ; v2@151.32,1624.63 53.09,1688.91 ; -61.5,1861.5 42,1758 42,1700 132,1610 v2(140,1610) 53.09,1688.91
$$$21603: J6.22 pad.95@2549.3,1084 | length 986.3
  Primary Side w12: pad.95@2549.3,1084 2549.3,971.1 2583.4,937 2618.97,937 2730,825.97 2730,640 J6.22@2640,550 ; J6.22@2625.31,570.23 2696.46,606.46 ; J6.22@2631.59,559.91 2696.46,606.46 ; J6.22@2649.91,541.59 2696.46,606.46 ; J6.22@2660.23,535.31 2696.46,606.46
$$$22520: pad.12@1640,800 pad.33@1446.94,1084 | length 558
  Primary Side w12: pad.33@1446.94,1084 1446.94,963.11 1578.85,831.2 1608.8,831.2 ; pad.12@1618.04,788.05 1608.8,831.2 ; pad.12@1629.55,792.26 1608.8,831.2 ; pad.12@1640,800 1608.8,831.2 ; pad.12@1647.74,810.45 1608.8,831.2 ; pad.12@1651.95,821.96 1608.8,831.2
$$$22525: pad.13@1740,800 pad.37@1509.93,1084 | length 447.5
  Primary Side w12: pad.37@1509.93,1084 1509.93,926.99 1585.92,851 1696.6,851 pad.13@1755.68,819.47 ; pad.13@1740,800 pad.13@1743.8,803.8
$$$22613: pad.16@2040,800 pad.43@1604.42,1084 | length 679.8
  Primary Side w12: pad.43@1604.42,1084 1600,1084 1600,995 1585,980 1585,932.53 1609.53,908 1939.6,908 1988.31,859.29 pad.16@2055.99,819.21 ; pad.16@2040,800 pad.16@2043.8,803.8
$$$22640: pad.17@2140,800 pad.45@1635.91,1084 | length 999.2
  Primary Side w12: pad.45@1635.91,1084 1630.96,1079.04 1630.96,994.66 1611.3,975 1611.3,945.3 1629.6,927 2070,927 2140,857 ; pad.17@2115.61,805.48 2140,857 ; pad.17@2127.08,801.48 2140,857 ; pad.17@2140,800 2140,857 ; pad.17@2152.92,801.48 2140,857 ; pad.17@2164.39,805.48 2140,857
$$$23065: pad.27@6440,550 pad.177@4638.59,1084 | length 2473.9
  Primary Side w12: pad.177@4638.59,1084 4638.59,995 4655,978.59 6011.41,978.59 pad.27@6440,550 6383.54,606.46 ; pad.27@6419.77,535.31 6383.54,606.46 ; pad.27@6430.09,541.59 6383.54,606.46 ; pad.27@6448.41,559.91 6383.54,606.46 ; pad.27@6454.69,570.23 6383.54,606.46
$$$26024: pad.1@540,800 pad.9@1068.98,1084 | length 1032
  Primary Side w12: pad.1@525.31,820.23 596.46,856.46 ; pad.1@531.59,809.91 596.46,856.46 ; pad.1@540,800 613,873 719.39,873 776.39,930 1027.6,930 1068.98,971.39 pad.9@1068.98,1084 ; pad.1@549.91,791.59 596.46,856.46 ; pad.1@560.23,785.31 596.46,856.46
$$$26042: pad.2@640,800 pad.11@1100.48,1084 | length 930.3
  Primary Side w12: pad.2@625.65,820.47 691.08,851.08 ; pad.2@631.67,809.98 691.08,851.08 ; pad.2@640,800 691.08,851.08 ; pad.2@649.98,791.67 691.08,851.08 ; pad.2@660.47,785.65 691.08,851.08 ; pad.11@1100.48,1084 1100.48,976.01 1030,905.53 798.92,905.53 744.47,851.08 691.08,851.08
$$$26048: pad.3@740,800 pad.13@1131.98,1084 | length 889.5
  Primary Side w12: pad.3@725.31,820.23 796.46,856.46 ; pad.3@731.59,809.91 796.46,856.46 ; pad.3@740,800 822,882 1033.34,882 1131.98,980.64 pad.13@1131.98,1084 ; pad.3@749.91,791.59 796.46,856.46 ; pad.3@760.23,785.31 796.46,856.46
$$$26058: pad.4@840,800 pad.15@1163.47,1084 | length 818.3
  Primary Side w12: pad.4@825.31,820.23 896.46,856.46 ; pad.4@831.59,809.91 896.46,856.46 ; pad.4@840,800 903,863 1041.21,863 1163.47,985.26 pad.15@1163.47,1084 ; pad.4@849.91,791.59 896.46,856.46 ; pad.4@860.23,785.31 896.46,856.46
$$$26066: pad.5@940,800 pad.17@1194.97,1084 | length 677.5
  Primary Side w12: pad.5@926.23,820.87 984,844 ; pad.5@931.82,810.1 984,844 ; pad.5@940,800 984,844 ; pad.5@950.1,791.82 984,844 ; pad.5@960.87,786.23 984,844 ; pad.17@1194.97,1084 1194.97,988.38 1159.59,953 1158.3,953 1049.3,844 984,844
$$$26070: pad.6@1040,800 pad.21@1257.96,1084 | length 409.2
  Primary Side w12: pad.6@1040,800 1036.2,803.8 1130.4,898 1184.6,898 1257.96,971.36 pad.21@1257.96,1084
$$$26081: pad.7@1140,800 pad.23@1289.46,1084 | length 349.2
  Primary Side w12: pad.7@1123.99,819.21 1192.06,859.66 1289.46,957.06 pad.23@1289.46,1084 ; pad.7@1136.2,803.8 pad.7@1140,800
$$$26086: pad.8@1240,800 pad.25@1320.95,1084 | length 585.5
  Primary Side w12: pad.8@1215.44,804.66 1240,867 ; pad.8@1227.06,801.26 1240,867 ; pad.8@1240,800 1240,870 1320.95,950.95 pad.25@1320.95,1084 ; pad.8@1252.94,801.26 1240,867 ; pad.8@1264.56,804.66 1240,867
$$$26090: pad.9@1340,800 pad.27@1352.45,1084 | length 557.2
  Primary Side w12: pad.9@1315.44,804.66 1340,867 ; pad.9@1327.06,801.26 1340,867 ; pad.9@1340,800 1340,927.55 1352.45,940 pad.27@1352.45,1084 ; pad.9@1352.94,801.26 1340,867 ; pad.9@1364.56,804.66 1340,867
$$$26098: pad.10@1440,800 pad.29@1383.94,1084 | length 465.4
  Primary Side w12: pad.29@1383.94,1084 1383.94,863.65 1443.8,803.8 pad.10@1440,800 ; pad.10@1449.06,809.33 1389.13,858.47 pad.10@1455.97,819.24
$$$26104: pad.11@1540,800 pad.31@1415.44,1084 | length 465.3
  Primary Side w12: pad.31@1415.44,1084 1415.44,939.43 1517.03,837.84 ; pad.11@1528.02,794.96 1517.03,837.84 ; pad.11@1540,800 1517.03,837.84 ; pad.11@1550,808.3 1517.03,837.84 ; pad.11@1556.84,818.48 1517.03,837.84
$$$26127: pad.14@1840,800 pad.39@1541.43,1084 | length 515.3
  Primary Side w12: pad.39@1541.43,1084 1541.43,922.37 1593.79,870 1777.6,870 1840,807.6 pad.14@1840,800
$$$26137: pad.15@1940,800 pad.41@1572.92,1084 | length 758.7
  Primary Side w12: pad.41@1572.92,1084 1570,1081.08 1570,1065 1575,1060 1575,1004 1563,992 1563,927.66 1601.66,889 1858.6,889 1943.8,803.8 pad.15@1940,800 ; pad.15@1949.06,809.32 1888.56,859.03 pad.15@1955.99,819.22
$$$26222: pad.1@540,1500 pad.12@1100.48,1217.86 | length 1064.8
  Primary Side w12: pad.1@525.31,1479.77 596.46,1443.54 ; pad.1@531.59,1490.09 596.46,1443.54 ; pad.1@540,1500 668,1372 995.91,1372 1013.91,1354 1080.6,1354 1100.48,1334.12 pad.12@1100.48,1217.86 ; pad.1@549.91,1508.41 596.46,1443.54 ; pad.1@560.23,1514.69 596.46,1443.54
$$$26237: pad.2@640,1500 pad.14@1131.98,1217.86 | length 993.6
  Primary Side w12: pad.2@625.31,1479.77 696.46,1443.54 ; pad.2@631.59,1490.09 696.46,1443.54 ; pad.2@640,1500 749,1391 1009.02,1391 1027.02,1373 1088.47,1373 1131.98,1329.49 pad.14@1131.98,1217.86 ; pad.2@649.91,1508.41 696.46,1443.54 ; pad.2@660.23,1514.69 696.46,1443.54
$$$26242: pad.3@740,1500 pad.16@1163.47,1217.86 | length 922.4
  Primary Side w12: pad.3@725.31,1479.77 796.46,1443.54 ; pad.3@731.59,1490.09 796.46,1443.54 ; pad.3@740,1500 830,1410 1021.91,1410 1039.91,1392 1096.34,1392 1163.47,1324.87 pad.16@1163.47,1217.86 ; pad.3@749.91,1508.41 796.46,1443.54 ; pad.3@760.23,1514.69 796.46,1443.54
$$$26246: pad.4@840,1500 pad.18@1194.97,1217.86 | length 851.2
  Primary Side w12: pad.4@825.31,1479.77 896.46,1443.54 ; pad.4@831.59,1490.09 896.46,1443.54 ; pad.4@840,1500 911,1429 1035.27,1429 1053.27,1411 1104.21,1411 1194.97,1320.24 pad.18@1194.97,1217.86 ; pad.4@849.91,1508.41 896.46,1443.54 ; pad.4@860.23,1514.69 896.46,1443.54
$$$26250: pad.5@940,1500 pad.20@1226.46,1217.86 | length 639.3
  Primary Side w12: pad.5@924.52,1480.37 965,1464.35 ; pad.5@930.59,1491.03 965,1464.35 ; pad.5@951.64,1505.79 965,1464.35 ; pad.20@1226.46,1217.86 1226.46,1315.61 1111.08,1431 1065.63,1431 1047.63,1449 980.35,1449 965,1464.35 ; 965,1464.35 939.39,1499.56 pad.5@940,1500 965,1464.35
